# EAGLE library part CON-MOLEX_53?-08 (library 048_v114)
CONNECTOR wire to board 1.25 mm (.049 inch) pitch header
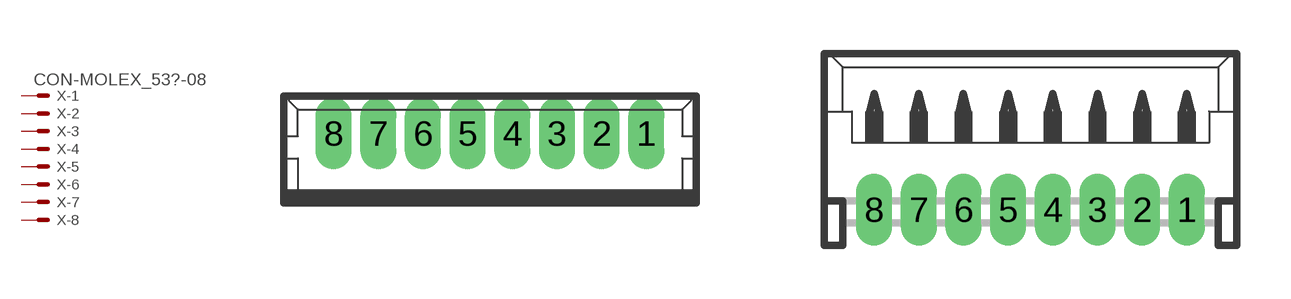
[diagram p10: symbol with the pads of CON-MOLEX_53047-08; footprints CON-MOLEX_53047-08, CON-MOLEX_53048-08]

Designator prefix X; gates -1=CON-MOLEX_MV -2=CON-MOLEX_M -3=CON-MOLEX_M -4=CON-MOLEX_M -5=CON-MOLEX_M -6=CON-MOLEX_M -7=CON-MOLEX_M -8=CON-MOLEX_M

## CON-MOLEX_53047-08  [CON-MOLEX_53047-08]
1  -1:S  pas
2  -2:S  pas
3  -3:S  pas
4  -4:S  pas
5  -5:S  pas
6  -6:S  pas
7  -7:S  pas
8  -8:S  pas

## CON-MOLEX_53048-08  [CON-MOLEX_53048-08]
Pads as for CON-MOLEX_53047-08

## CON-MOLEX_53261-08  [CON-MOLEX_53261-08]
Pads as for CON-MOLEX_53047-08

## CON-MOLEX_53398-08  [CON-MOLEX_53398-08]
Pads as for CON-MOLEX_53047-08

## Footprint CON-MOLEX_53047-08 (pad centres in mm)
CONNECTOR wire to board 1.25 mm (.049 inch) pitch header straight Sourcxe: http://www.molex.com/pdm_docs/sd/530470210_sd.pdf
drill 0.5 pad 0.698 long: 1 4.375,0.45; 2 3.125,0.45; 3 1.875,0.45; 4 0.625,0.45; 5 -0.625,0.45; 6 -1.875,0.45; 7 -3.125,0.45; 8 -4.375,0.45

## Footprint CON-MOLEX_53048-08 (pad centres in mm)
CONNECTOR wire to board 1.25 mm (.049 inch) pitch header right angle
drill 0.5 pad 0.698 long: 1 4.375,-1.25; 2 3.125,-1.25; 3 1.875,-1.25; 4 0.625,-1.25; 5 -0.625,-1.25; 6 -1.875,-1.25; 7 -3.125,-1.25; 8 -4.375,-1.25

## Footprint CON-MOLEX_53261-08 (pad centres in mm)
CONNECTOR wire to board 1.25 mm (.049 inch) pitch header SMT right angle
smd 0.8 x 2: 1 4.375,-2.5; 2 3.125,-2.5; 3 1.875,-2.5; 4 0.625,-2.5; 5 -0.625,-2.5; 6 -1.875,-2.5; 7 -3.125,-2.5; 8 -4.375,-2.5
smd 2.1 x 3: S1 6.875,0.625; S2 -6.875,0.625

## Footprint CON-MOLEX_53398-08 (pad centres in mm)
CONNECTOR wire to board 1.25 mm (.049 inch) pitch header SMT straight
smd 0.8 x 1.8: 1 4.375,-2.5; 2 3.125,-2.5; 3 1.875,-2.5; 4 0.625,-2.5; 5 -0.625,-2.5; 6 -1.875,-2.5; 7 -3.125,-2.5; 8 -4.375,-2.5
smd 2.1 x 3: S1 6.875,0.625; S2 -6.875,0.625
